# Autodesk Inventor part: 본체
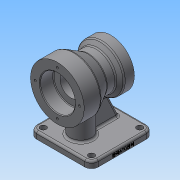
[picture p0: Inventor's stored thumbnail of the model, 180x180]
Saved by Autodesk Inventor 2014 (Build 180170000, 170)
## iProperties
Created: 2019-01
Part Number: 본체
Material: 일반
Document SubType Name: Modeling
Designer: NET
Density: 1 g/cm^3
Appearance: 기본값
Author: NET
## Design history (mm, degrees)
sketch "스케치1"
  geometry: L1 (0, 0)-(25, 0); L2 (25, 0)-(25, 40); L3 (25, 40)-(0, 40); L4 (0, 40)-(0, 0); L5 (25, 40)-(45.785, 28); L6 (45.785, 28)-(59.126, 28); L7 (59.126, 28)-(65, 35); L8 (65, 35)-(80, 35); L9 (80, 35)-(80, 0); L10 (80, 0)-(25, 0)
  constraints: 20 end point, 3 parallel, 3 perpendicular, 1 collinear, 1 horizontal
  dimensions: "d0" = 80 distance between parallel lines of L9 L4; "d1" = 25 distance of L2.end L3.end; "d2" = 15 distance of L7.end L8.end; "d3" = 80 diameter of L3 L1; "d4" = 56 diameter of L6 L10; "d5" = 30 deg angle of L6 L5; "d6" = 50 deg angle of L6 L7; "d7" = 70 diameter of L8 L10
revolve "회전1" sketch "스케치1" stored, may be unused: angle "d8" = 90 deg
node "작업 평면1"
sketch "스케치2"
  geometry: L1 (-5, -46)-(-97, -46); L2 (-97, -46)-(-97, 46); L3 (-97, 46)-(-5, 46); L4 (-5, 46)-(-5, -46); 1 further point
  constraints: 8 end point, 2 parallel, 1 horizontal, 1 perpendicular
  dimensions: "d10" = 92 distance of L1.end L2.end; "d11" = 92 distance of L1.start L1.end; "d12" = 46 distance from line of point (0, 0) L1; "d13" = 5 distance from line of point (0, 0) L4
extrude "돌출1" join sketch "스케치2" distance "d14" = 10; taper "d15" = 0 deg
fillet "모깎기1" dims "d16" = 10
sketch "스케치3"
  geometry: L1 (5, 36)-(5, -36) reference; C1 r 16 at (35, 0); 1 further point
  constraints: 1 centre point
  dimensions: "d17" = 32 diameter of C1; "d18" = 30 distance from line of L1 C1.centre; "d19" = 0 vertical distance of point (0, 0) C1.centre
extrude "돌출2" join sketch "스케치3" stored distance "d20" = 10; taper "d21" = 0 deg
sketch "스케치5"
  geometry: L1 (87, -70)-(97, -70) reference; L2 (15, -70)-(87, -70) reference; L3 (97, -80)-(97, -70) reference; L4 (51, -70)-(51, -28) reference; L5 (44.431, -70)-(87, -70); L6 (87, -70)-(44.431, 21.29); L7 (44.431, 21.29)-(44.431, -70); 1 further point
  constraints: 6 end point, 2 perpendicular
  dimensions: "d25" = 10 distance from line of L3 L5.end; "d26" = 0 distance between parallel lines of L2 L5; "d27" = 25 deg angle of L3 L6; "d32" = 6.56932 distance between parallel lines of L4 L7
extrude "돌출3" join sketch "스케치5" stored distance "d28" = 10; taper "d29" = 0 deg
fillet "모깎기2" dims "d30" = 3
fillet "모깎기4" dims "d33" = 3
fillet "모깎기5" dims "d34" = 3
sketch "스케치6"
  geometry: A1 r 7 centre (15, -36) between (8, -36) and (15, -43) reference; A2 r 7 centre (87, -36) between (87, -43) and (94, -36) reference; A3 r 7 centre (87, 36) between (94, 36) and (87, 43) reference; A4 r 7 centre (15, 36) between (15, 43) and (8, 36) reference; 5 further points
  constraints: 4 coincident
hole "구멍1" sketch "스케치6" at (15, 36), (87, 36), (87, -36), (15, -36) diameter "d35" = 9; stored, may be unused: countersink angle "d39" = 90 deg, drill point angle "d41" = 118 deg; dims "d36" = 6, "d37" = 4, "d38" = 2, "d40" = 8
sketch "스케치7"
  geometry: L1 (0, 26)-(20, 26); L2 (20, 26)-(20, 0); L3 (20, 0)-(0, 0); L4 (0, 0)-(0, 26); L5 (20, 16)-(63, 16); L6 (63, 16)-(63, 0); L7 (63, 0)-(20, 0); L8 (20, 0)-(20, 16); L9 (63, 0)-(80, 0); L10 (80, 0)-(80, 20); L11 (80, 20)-(63, 20); L12 (63, 20)-(63, 0); L13 (0, -40)-(0, 40) reference; L14 (80, -35)-(80, 35) reference; 1 further point
  constraints: 24 end point, 6 parallel, 3 horizontal, 3 perpendicular, 1 point on line
  dimensions: "d42" = 0 distance between parallel lines of L13 L4; "d44" = 0 distance between parallel lines of L14 L10; "d45" = 0 distance from line of point (0, 0) L3; "d46" = 26 distance between parallel lines of L3 L1; "d47" = 20 distance between parallel lines of L9 L11; "d48" = 16 distance between parallel lines of L7 L5; "d49" = 20 distance of L1.start L1.end; "d50" = 17 distance of L10.end L11.end
revolve "회전2" sketch "스케치7" stored, may be unused: angle "d51" = 90 deg
sketch "스케치8"
  geometry: C1 r 40 at (0, 0) reference; A1 r 33 centre (0, 0) between (0, 33) and (33, 0); 2 further points
  constraints: 4 point on circle, 1 centre point, 1 coincident
  dimensions: "d52" = 66 diameter of A1
hole "구멍2" sketch "스케치8" at (0, 33), (33, 0), (0, -33), (-33, 0) diameter "d53" = 3.242; stored, may be unused: countersink angle "d57" = 90 deg, drill point angle "d59" = 118 deg; dims "d54" = 9, "d55" = 4, "d56" = 2, "d58" = 11
sketch "스케치9"
  geometry: C1 r 35 at (0, 0) reference; A1 r 27.5 centre (0, 0) between (0, 27.5) and (27.5, 0); 2 further points
  constraints: 4 point on circle, 1 centre point, 1 coincident
  dimensions: "d60" = 55 diameter of A1
hole "구멍3" sketch "스케치9" at (0, 27.5), (27.5, 0), (0, -27.5), (-27.5, 0) diameter "d61" = 3.242; stored, may be unused: countersink angle "d65" = 90 deg, drill point angle "d67" = 118 deg; dims "d62" = 9, "d63" = 4, "d64" = 2, "d66" = 11
chamfer "모따기1" distance "d68" = 1; stored, may be unused: second distance "d69" = 2, angle "d70" = 45 deg
fillet "모깎기6" dims "d71" = 1
fillet "모깎기7" dims "d72" = 0.6
sketch "스케치10"
  geometry: L1 (-10, 7)-(-10, 0) reference; L2 (82, 0)-(72, 0) reference; 2 further points
  constraints: 1 other
  dimensions: "d73" = 46 distance from line of L1 point (36, 4); "d74" = 4 distance from line of L2 point (36, 4)
feature "엠보싱1" sketch "스케치10" dims "d16" = 10, "d75" = 0.5, "d76" = 0
fillet "모깎기8" dims "d77" = 3
node "솔리드1"
